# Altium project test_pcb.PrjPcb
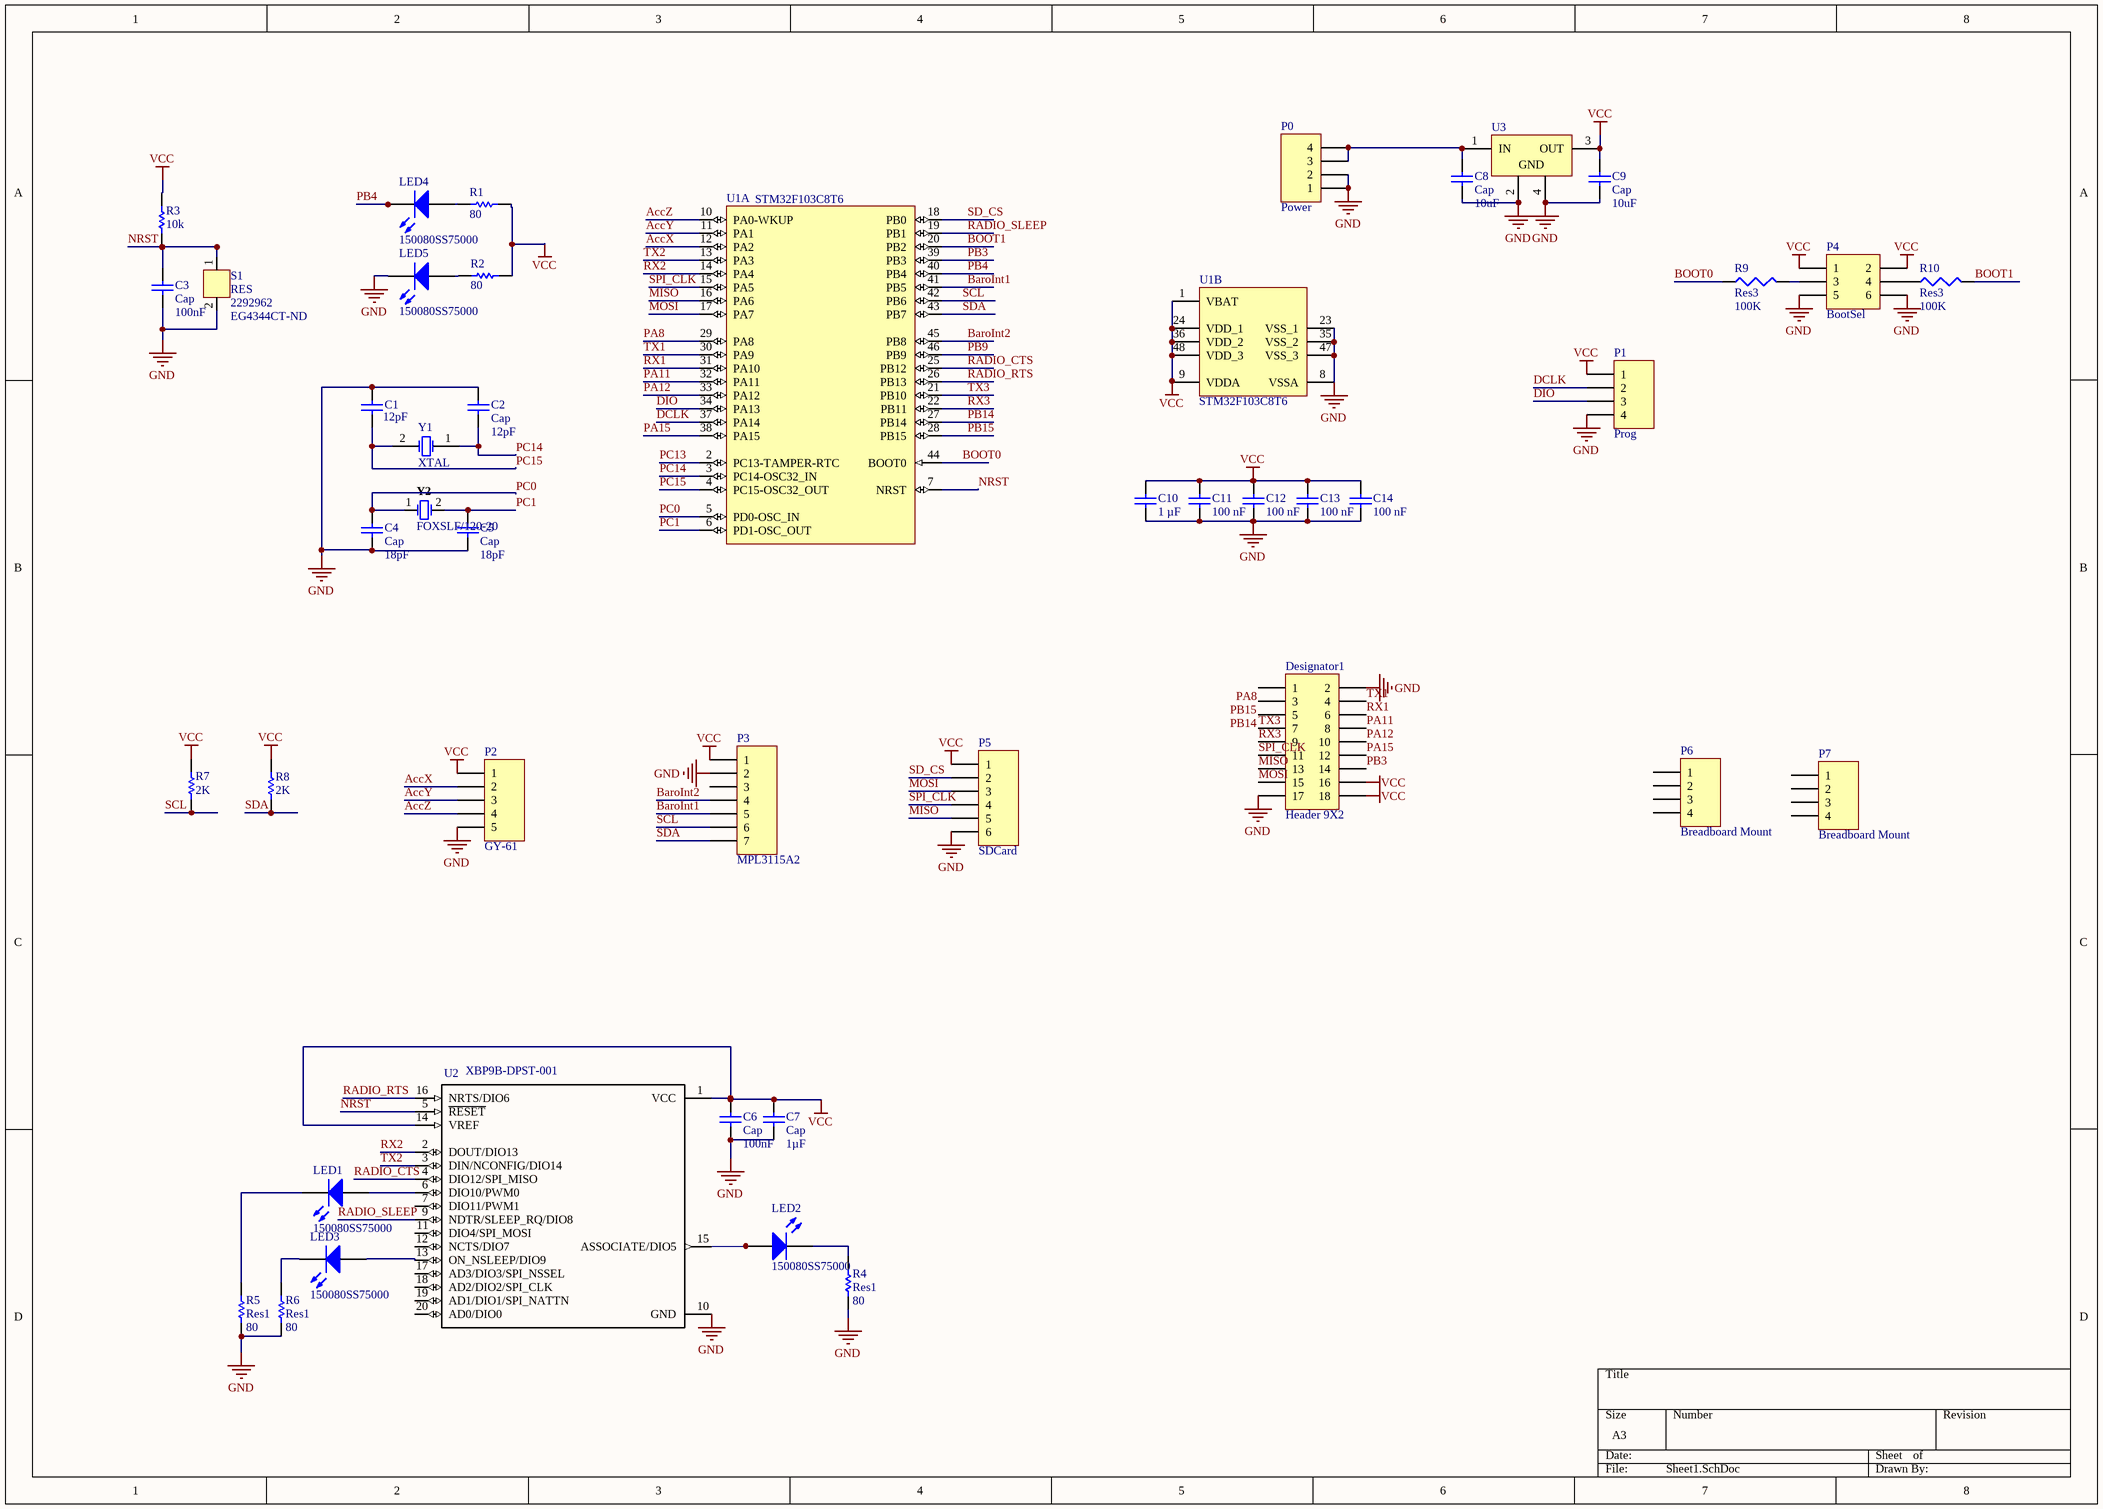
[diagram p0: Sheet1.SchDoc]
1 sheet, 44 parts. Net scope: global (net labels, ports and power ports of the same name join across sheets).
Board files: PCB1.PcbDoc, PCB1_twoLayer.PcbDoc

## Sheet Sheet1.SchDoc
size A3

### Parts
C1  value 12pF  [6-0805_N]  (hidden comment: Cap)
C2  Cap  value 12pF  [6-0805_N]
C3  Cap  value 100nF  [6-0805_N]
C4  Cap  value 18pF  [6-0805_N]
C5  Cap  value 18pF  [6-0805_N]
C6  Cap  value 100nF  [6-0805_N]
C7  Cap  value 1µF  [6-0805_N]
C8  Cap  value 10uF  [6-0805_N]
C9  Cap  value 10uF  [6-0805_N]
C10  1 µF  [CAPC1609X100X15NL20]
C11  100 nF  [SAMS-C0603-2_M]
C12  100 nF  [SAMS-C0603-2_M]
C13  100 nF  [SAMS-C0603-2_M]
C14  100 nF  [SAMS-C0603-2_M]
Designator1  Header 9X2  [HDR2X9]
LED1  150080SS75000  [0805_A]
LED2  150080SS75000  [0805_A]
LED3  150080SS75000  [0805_A]
LED4  150080SS75000  [0805_A]
LED5  150080SS75000  [0805_A]
P0  Power  [HDR1X4]
P1  Prog  [HDR1X4]
P2  GY-61  [HDR1X5]
P3  MPL3115A2  [HDR1X7]
P4  BootSel  [HDR2X3]
P5  SDCard  [HDR1X6]
P6  Breadboard Mount  [HDR1X4]
P7  Breadboard Mount  [HDR1X4]
R1  value 80  [6-0805_N]  (hidden comment: Res1)
R2  value 80  [6-0805_N]  (hidden comment: Res1)
R3  value 10k  [6-0805_N]  (hidden comment: Res1)
R4  Res1  value 80  [6-0805_N]
R5  Res1  value 80  [6-0805_N]
R6  Res1  value 80  [6-0805_N]
R7  value 2K  [6-0805_N]  (hidden comment: Res1)
R8  value 2K  [6-0805_N]  (hidden comment: Res1)
R9  Res3  value 100K  [J1-0603]
R10  Res3  value 100K  [J1-0603]
S1  RES  Supplier Part Number 1: 2292962  Supplier Part Number 2: EG4344CT-ND  [SWITCH- TL1015AF160QG]
U1  STM32F103C8T6  [STM-LQFP48_N]  (parts A,B of 2)
U2  XBP9B-DPST-001  [DIP2200W51P200L3294H279Q20P]
U3  TL1963A-33DCYR  [DCY0004A_N]  (value not drawn)
Y1  XTAL  [HDR1X2]
Y2  FOXSLF/120-20  [FOX-FOXSLF-2_V]

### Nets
GND: C1.2 C2.2 C3.1 C4.1 C5.1 C6.1 C7.1 C8.1 C9.1 C10.1 C11.2 C12.2 C13.2 C14.2 Designator1.2 Designator1.17 LED5.1(K) P0.1 P0.2 P1.4 P2.5 P3.2 P4.5 P4.6 P5.6 R4.1 R5.1 R6.1 S1.2 U1.8(VSSA) U1.23(VSS_1) U1.35(VSS_2) U1.47(VSS_3) U2.10(GND) U3.2(GND) U3.4(GND)
VCC: C6.2 C7.2 C9.2 C10.2 C11.1 C12.1 C13.1 C14.1 Designator1.16 Designator1.18 P1.1 P2.1 P3.1 P4.1 P4.2 P5.1 R1.2 R2.2 R3.2 R7.2 R8.2 U1.1(VBAT) U1.9(VDDA) U1.24(VDD_1) U1.36(VDD_2) U1.48(VDD_3) U2.1(VCC) U2.14(VREF) U3.3(OUT)
 PA8: Designator1.1 U1.29(PA8)  [also labelled PA8]
AccX: P2.2 U1.12(PA2)
AccY: P2.3 U1.11(PA1)
AccZ: P2.4 U1.10(PA0-WKUP)
BaroInt1: P3.5 U1.41(PB5)
BaroInt2: P3.4 U1.45(PB8)
BOOT0: R9.1 U1.44(BOOT0)
BOOT1: R10.2 U1.20(PB2)
DCLK: P1.2 U1.37(PA14)
DIO: P1.3 U1.34(PA13)
MISO: Designator1.13 P5.5 U1.16(PA6)
MOSI: Designator1.15 P5.3 U1.17(PA7)
NRST: C3.2 R3.1 S1.1 U1.7(NRST) U2.5(~{RESET})
PA11: Designator1.8 U1.32(PA11)
PA12: Designator1.10 U1.33(PA12)
PA15: Designator1.12 U1.38(PA15)
PB3: Designator1.14 U1.39(PB3)
PB4: LED4.1(K) U1.40(PB4)
PB9: U1.46(PB9)
PB14: Designator1.5 U1.27(PB14)
PB15: Designator1.3 U1.28(PB15)
PC0: C4.2 U1.5(PD0-OSC_IN) Y2.1
PC1: C5.2 U1.6(PD1-OSC_OUT) Y2.2
PC13: U1.2(PC13-TAMPER-RTC)
PC14: C2.1 U1.3(PC14-OSC32_IN) Y1.1(OSC1)
PC15: C1.1 U1.4(PC15-OSC32_OUT) Y1.2(OSC2)
RADIO_CTS: U1.25(PB12) U2.4(DIO12/SPI_MISO)
RADIO_RTS: U1.26(PB13) U2.16(NRTS/DIO6)
RADIO_SLEEP: U1.19(PB1) U2.9(NDTR/SLEEP_RQ/DIO8)
RX1: Designator1.6 U1.31(PA10)
RX2: U1.14(PA4) U2.2(DOUT/DIO13)
RX3: Designator1.9 U1.22(PB11)
SCL: P3.6 R7.1 U1.42(PB6)
SD_CS: P5.2 U1.18(PB0)
SDA: P3.7 R8.1 U1.43(PB7)
SPI_CLK: Designator1.11 P5.4 U1.15(PA5)
TX1: Designator1.4 U1.30(PA9)
TX2: U1.13(PA3) U2.3(DIN/NCONFIG/DIO14)
TX3: Designator1.7 U1.21(PB10)
NetC8_2: C8.2 P0.3 P0.4 U3.1(IN)
NetLED1_1: LED1.1(K) R5.2
NetLED1_2: LED1.2(A) U2.6(DIO10/PWM0)
NetLED2_1: LED2.1(K) R4.2
NetLED2_2: LED2.2(A) U2.15(ASSOCIATE/DIO5)
NetLED3_1: LED3.1(K) R6.2
NetLED3_2: LED3.2(A) U2.13(ON_NSLEEP/DIO9)
NetLED4_2: LED4.2(A) R1.1
NetLED5_2: LED5.2(A) R2.1
NetP4_3: P4.3 R9.2
NetP4_4: P4.4 R10.1

Not connected (* = marked no-connect by the designer): P3 3; P6 1 2 3 4; P7 1 2 3 4; U2 7(DIO11/PWM1) 11(DIO4/SPI_MOSI) 12(NCTS/DIO7) 17(AD3/DIO3/SPI_NSSEL) 18(AD2/DIO2/SPI_CLK) 19(AD1/DIO1/SPI_NATTN) 20(AD0/DIO0)

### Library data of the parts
C1-C9 = Cap: Capacitor
C10 = CMP-2006-00184-1: Part Number: TACL105K010XTA; Manufacturer: AVX Interconnect / Elco; Value: 1µF
C11-C14 = CMP-2000-05332-1: Multi-layer Ceramic Capacitor, -55 to 125 degC, 2-Pin SMD (0603), RoHS, Tape and Reel; Manufacturer: Samsung Electro-Mechanics; Capacitance: 0.1µF; Rated Voltage: 50V; Dielectric: X7R; Tolerance (%): ±10%; Value: 100nF
Designator1 = Header 9X2: Header, 9-Pin, Dual row
LED1-LED5 = CMP-1426-00010-1: SMD mono-color Chip LED, WL-SMCW, Super Red; Manufacturer: Wuerth Elektronik
P0 P6 P7 = Header 4: Header, 4-Pin
P1 = Header 4: Programming header like on Blue Pill
P2 = Header 5: GY-61 breakout board
P3 = Header 7: Adafruit MPL3115A2 breakout board
P4 = Header 3X2: Header, 3-Pin, Dual row
P5 = Header 6: Header, 6-Pin
R1-R8 = Res1: Resistor
R9 R10 = Res3: Resistor
S1 = SWITCH_2PIN: Switch
U1 = STM32F103C8T6: ARM Cortex-M3 32-bit MCU, 64 KB Flash, 20 KB Internal RAM, 37 I/Os, 48-pin LQFP, -40 to 85 degC, Tray; A/D Converter: 2x12-bit (10 Channel); FLASH Size (Prog) (kB): 64; I/Os (High Current): 37; Internal RAM Size (kB): 20; Operating Frequency(F) (Processor speed) (MHz): 72; Supply Voltage(Vcc) min (V): 2
U2 = XBP9B-DPST-001: XBee-PRO 900HP _S3B_ Point2Multipoint, 900MHz, 250mW, RPSMA, 10Kbps; MF: Digi International
U3 = CMP-0395-00535-2: Single Output Low Noise LDO, 1.5 A, Fixed 3.3 V Output, 2.1 to 20 V Input, 4-pin SOT-223 (DCY), -40 to 125 degC, Green (RoHS & no Sb/Br); Manufacturer: Texas Instruments; Vout Adj(Min)(V): 3.3; Vin(Max)(V): 20; SubFamily: Single Channel LDO; Iq(Typ)(mA): 1; Iout(Max)(A): 1.5; Vin(Min)(V): 2.1; Vdo(Typ)(mV): 340; Accuracy(%): 3
Y1 = XTAL: Crystal Oscillator 32.768 kHz
Y2 = CMP-1749-00004-1: Resistance Weld Thru-Hole Crystal, 12 MHz, +/-30 ppm, -20 to 70 degC, 2-Pin THD, RoHS, Bulk; Elements: 1; Rds On Max: 115 mohm; Typical Rise Time: 90 ns; Max Power Dissipation: 2.5 W; Case\Package: TO-251-3; Input Capacitance: 350 pF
